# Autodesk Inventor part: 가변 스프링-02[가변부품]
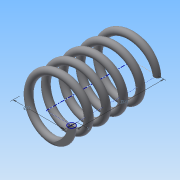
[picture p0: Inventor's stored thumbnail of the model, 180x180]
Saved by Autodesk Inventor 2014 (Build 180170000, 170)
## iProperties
Created: 2015-09
Part Number: 가변 스프링-02[가변부품]
Material: 강철, 탄소
Document SubType Name: Modeling
Designer: study
Density: 1 g/cm^3
Appearance: 반연마
Author: study
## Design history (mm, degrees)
sketch "스케치1"
  geometry: L1 (0, 0)-(11, 0); L2 (11, 0)-(11, 25.358); L3 (11, 25.358)-(0, 25.358); L4 (0, 25.358)-(0, 0); C1 r 1.5 at (11, 0)
  constraints: 8 end point, 2 parallel, 1 centre point, 1 coincident, 1 horizontal, 1 perpendicular
  dimensions: "d0" = 3 diameter of C1; "d1" = 22 diameter of L2 L4; "d2" = 25.35829 distance of L1.end L2.end (derived)
feature "코일1" sketch "스케치1" pitch "d3" = 10; turns "d5" = 5; dims "d4" = 25.35829 (= d2), "d6" = 0, angle "d7" = 90 deg, angle "d8" = 90 deg, "d9" = 0, "d10" = 0
node "작업 평면1"
sketch "스케치2"
  geometry: L1 (-12.5, 0)-(-9.5, 0) reference; 1 further point
  constraints: 1 horizontal alignment
extrude "돌출1" cut sketch "스케치2" distance "d12" = 10; taper "d13" = 0 deg
node "작업 평면2"
sketch "스케치3"
  geometry: L1 (-9.5, 0)-(-12.5, 0) reference; L2 (-9.5, 0)-(-12.5, 0) reference; 1 further point
  constraints: 2 horizontal alignment
extrude "돌출2" cut sketch "스케치3" distance "d15" = 10; taper "d16" = 0 deg
node "솔리드1"
node "절단 모서리 투영1"
node "절단 모서리 투영2"
node "절단 모서리 투영3"
other parameters: "d11" = 0, "d14" = 25.35829 (= d2)
